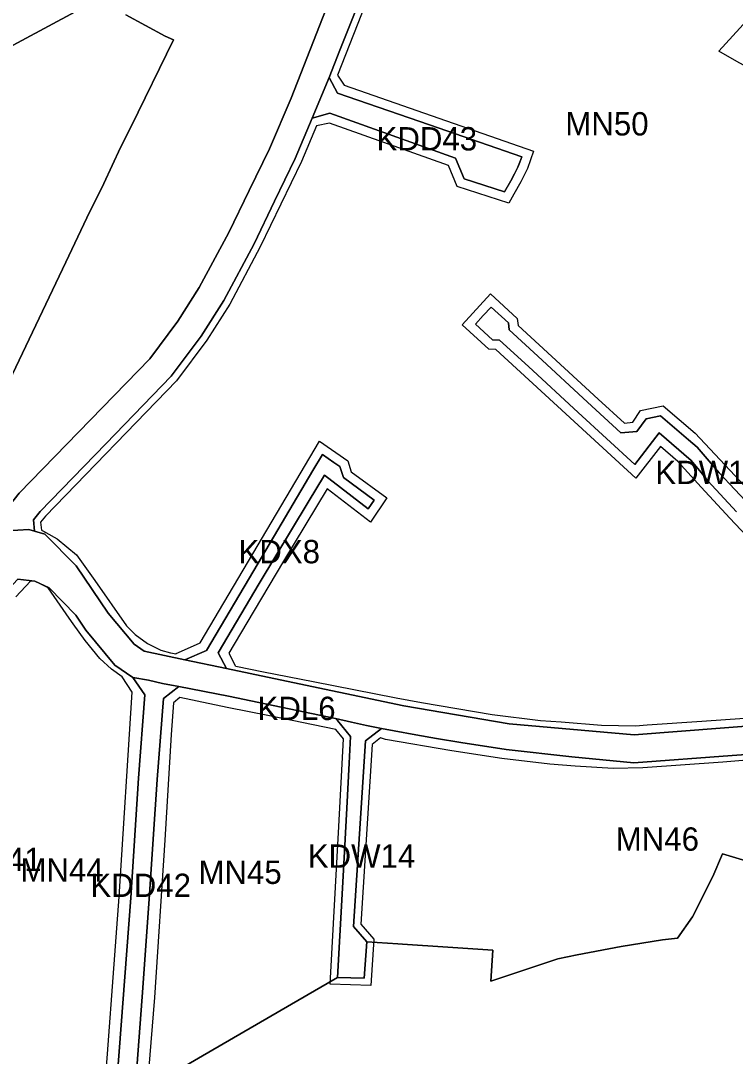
# Model space of a CAD drawing. Extents: x 7428841 to 7433518, y 5545054 to 5546840.
# Drawn here: x 7432155.6 to 7432461.8, y 5545406.8 to 5545850.4 of the extents above; entities that cross this region are included whole.
import ezdxf

# ---------------------------------------------------------------- set-up
doc = ezdxf.new("R2010")
doc.units = 0
for name, color, linetype in [('linie_rozgraniczajace', 7, 'Continuous'), ('linie_zabudowy_nieprzekraczalne', 7, 'Continuous'), ('oznaczenia_przeznaczen', 7, 'Continuous')]:
    doc.layers.add(name, color=color, linetype=linetype)

msp = doc.modelspace()

# ---------------------------------------------------------------- linework, layer by layer
at = {"layer": 'linie_rozgraniczajace'}
for points in [[(7432132.18, 5545621.69), (7432147.9, 5545639.12), (7432154.88, 5545648.03), (7432210.86, 5545705.54), (7432222.9, 5545721.64), (7432232.08, 5545736.14), (7432244.76, 5545759.7), (7432253.45, 5545777.62), (7432262.14, 5545795.55), (7432271.44, 5545817.17), (7432287.75, 5545858.73), (7432313.15, 5545921.27), (7432332.96, 5545968.95), (7432347.45, 5546006.55), (7432352.33, 5546020.89), (7432357.2, 5546035.24), (7432363.75, 5546056.3), (7432370.28, 5546073.1), (7432379.89, 5546097.52)], [(7432188.47, 5545859.56), (7432146.36, 5545836.73), (7432135.07, 5545830.88), (7432134.66, 5545831.89), (7432125.88, 5545827.16), (7432101.56, 5545814.32), (7432079.45, 5545802.66), (7432010.61, 5545766.29), (7431989.91, 5545755.55), (7431989.48, 5545756.43), (7431983.69, 5545768.63), (7431979.69, 5545777.2), (7431976.57, 5545783.86), (7431971.71, 5545794.23)], [(7432146.36, 5545836.73), (7432188.47, 5545859.56)], [(7432287.75, 5545858.73), (7432271.44, 5545817.17), (7432262.14, 5545795.55), (7432253.45, 5545777.62), (7432244.76, 5545759.7), (7432232.08, 5545736.14), (7432222.9, 5545721.64), (7432210.86, 5545705.54), (7432154.88, 5545648.03), (7432147.9, 5545639.12), (7432132.18, 5545621.69), (7432124.12, 5545622.82), (7432124.01, 5545622.95), (7432120.53, 5545626.94), (7432114.08, 5545634.7), (7432107.63, 5545642.46), (7432103.72, 5545647.14)], [(7432103.72, 5545647.14), (7432115.61, 5545651.14), (7432124.15, 5545655.2), (7432129.9, 5545658.64), (7432133.99, 5545663.57), (7432139.05, 5545671.94), (7432174.91, 5545747.04), (7432183.86, 5545765.9), (7432191.2, 5545780.73), (7432198.41, 5545796.09), (7432202.91, 5545805.04), (7432221.07, 5545842.2), (7432217.5, 5545843.79), (7432200.67, 5545852.98)], [(7432298.89, 5545854.26), (7432292.35, 5545837.77), (7432287.69, 5545826.02), (7432280.47, 5545808.59), (7432273.19, 5545791.34), (7432264.38, 5545773.09), (7432255.56, 5545754.84), (7432242.56, 5545730.56), (7432232.89, 5545715.25), (7432220.1, 5545698.07), (7432192.02, 5545669.12), (7432163.94, 5545640.18), (7432161, 5545636.55), (7432161.55, 5545631.78), (7432159.07, 5545632.52), (7432149.7, 5545631.91), (7432134.84, 5545623.57), (7432132.18, 5545621.69)], [(7432200.67, 5545852.98), (7432217.5, 5545843.79), (7432221.07, 5545842.2), (7432202.91, 5545805.04), (7432198.41, 5545796.09), (7432191.2, 5545780.73), (7432183.86, 5545765.9), (7432174.91, 5545747.04), (7432139.05, 5545671.94)], [(7432161, 5545636.55), (7432163.94, 5545640.18), (7432192.02, 5545669.12), (7432220.1, 5545698.07), (7432232.89, 5545715.25), (7432242.56, 5545730.56), (7432255.56, 5545754.84), (7432264.38, 5545773.09), (7432273.19, 5545791.34), (7432280.47, 5545808.59), (7432288.02, 5545810.74), (7432341.82, 5545791.55), (7432345.58, 5545782.71), (7432362.91, 5545777.13), (7432365.52, 5545781.77), (7432367.15, 5545784.84), (7432368.55, 5545787.63), (7432369.45, 5545789.78), (7432370.26, 5545792.08), (7432330.81, 5545805.75), (7432291.36, 5545819.41), (7432287.69, 5545826.02), (7432292.35, 5545837.77), (7432298.89, 5545854.26)], [(7432468.21, 5545642.48), (7432454.85, 5545656.77), (7432445.49, 5545667.66), (7432441.75, 5545670.86), (7432429.75, 5545681.15), (7432423.63, 5545679.82), (7432419.51, 5545674.46), (7432412.78, 5545673.88), (7432398.5, 5545687.02), (7432377.15, 5545706.66), (7432364.82, 5545718), (7432364.53, 5545721), (7432357.17, 5545727.76), (7432353.79, 5545724.08), (7432350.4, 5545720.4), (7432357.76, 5545713.64), (7432360.76, 5545713.6), (7432373.1, 5545702.24), (7432394.43, 5545682.61), (7432418.67, 5545660.3), (7432429.09, 5545673.81), (7432442.81, 5545662.06), (7432447.1, 5545656.91), (7432450.07, 5545653.35), (7432462.29, 5545640.03)], [(7432462.29, 5545640.03), (7432450.07, 5545653.35), (7432447.1, 5545656.91), (7432442.81, 5545662.06), (7432429.09, 5545673.81), (7432418.67, 5545660.3), (7432394.43, 5545682.61), (7432373.1, 5545702.24), (7432360.76, 5545713.6), (7432357.76, 5545713.64), (7432350.4, 5545720.4), (7432353.79, 5545724.08), (7432357.17, 5545727.76), (7432364.53, 5545721), (7432364.82, 5545718), (7432377.15, 5545706.66), (7432398.5, 5545687.02), (7432412.78, 5545673.88), (7432419.51, 5545674.46), (7432423.63, 5545679.82), (7432429.75, 5545681.15), (7432441.75, 5545670.86), (7432445.49, 5545667.66), (7432454.85, 5545656.77), (7432468.21, 5545642.48)], [(7432495.96, 5545550.47), (7432457.17, 5545547.49), (7432418.37, 5545544.51), (7432364.94, 5545549.16), (7432319.77, 5545556.99), (7432264.11, 5545568.64), (7432243.74, 5545572.89), (7432240.16, 5545579.64), (7432257.77, 5545609.34), (7432278.79, 5545644.13), (7432285.8, 5545655.72), (7432304.5, 5545641.34), (7432307.03, 5545645.05), (7432293.82, 5545654.7), (7432292.32, 5545659.42), (7432289.8, 5545661.17), (7432284.92, 5545664.56), (7432280.69, 5545657.77), (7432257.34, 5545617.98), (7432235.25, 5545580.69), (7432225.91, 5545576.62), (7432208.45, 5545580.28), (7432204.14, 5545583.28), (7432193.05, 5545596.6), (7432186.19, 5545606.77), (7432179.32, 5545616.95), (7432165.95, 5545630.47), (7432161.55, 5545631.78), (7432161, 5545636.55)], [(7432149.7, 5545631.91), (7432159.07, 5545632.52), (7432161.55, 5545631.78), (7432165.95, 5545630.47), (7432179.32, 5545616.95), (7432186.19, 5545606.77), (7432193.05, 5545596.6), (7432204.14, 5545583.28), (7432208.45, 5545580.28), (7432225.91, 5545576.62), (7432243.74, 5545572.89), (7432264.11, 5545568.64), (7432319.77, 5545556.99), (7432364.94, 5545549.16), (7432418.37, 5545544.51), (7432457.17, 5545547.49), (7432495.96, 5545550.47)], [(7432138.74, 5545379.48), (7432142.98, 5545436.66), (7432146.31, 5545480.82), (7432148.15, 5545499.91), (7432149.67, 5545528.57), (7432149.18, 5545545.32), (7432149.02, 5545565.9), (7432148.85, 5545586.48), (7432148.59, 5545598.65), (7432148.5, 5545604.9), (7432154.28, 5545611.17), (7432161.6, 5545610.32), (7432167.75, 5545607.49), (7432179.14, 5545595.76), (7432183.44, 5545589.39), (7432195.95, 5545574.36), (7432203.6, 5545569.04), (7432208.81, 5545561.69), (7432206.08, 5545525.88), (7432202.71, 5545474.72), (7432196.1, 5545386.25)], [(7432303.7, 5545548.56), (7432297.3, 5545549.97), (7432290.42, 5545551.44), (7432283.54, 5545552.91), (7432244.58, 5545561.06), (7432223.28, 5545565.18), (7432216.33, 5545566.52), (7432210.29, 5545567.85), (7432203.6, 5545569.04), (7432195.95, 5545574.36), (7432183.44, 5545589.39), (7432179.14, 5545595.76), (7432167.75, 5545607.49), (7432161.6, 5545610.32), (7432154.28, 5545611.17)], [(7432483.05, 5545485.51), (7432456.34, 5545493.47), (7432452.13, 5545483.85), (7432443.43, 5545466.55), (7432436.98, 5545457.38), (7432430.58, 5545456.64), (7432412.8, 5545453.79), (7432394.07, 5545450.22), (7432385.79, 5545448.51), (7432356.96, 5545439.01), (7432357.94, 5545452.26), (7432338.58, 5545453.55), (7432319.23, 5545454.85), (7432317.12, 5545454.99), (7432303.84, 5545455.89), (7432298.23, 5545462.43), (7432299.92, 5545488.83), (7432303.27, 5545541.94), (7432310.18, 5545547.28), (7432315.59, 5545546.21), (7432324.92, 5545544.5), (7432333.73, 5545542.87), (7432344.16, 5545541.23), (7432363.52, 5545538.18), (7432391.68, 5545535.1), (7432418.31, 5545532.47), (7432460.41, 5545535.59), (7432502.51, 5545538.7)], [(7432502.51, 5545538.7), (7432460.41, 5545535.59), (7432418.31, 5545532.47), (7432391.68, 5545535.1), (7432363.52, 5545538.18), (7432344.16, 5545541.23), (7432333.73, 5545542.87), (7432324.92, 5545544.5), (7432315.59, 5545546.21), (7432310.18, 5545547.28), (7432303.7, 5545548.56)], [(7432209.79, 5545393.18), (7432233.45, 5545406.94), (7432274.26, 5545430.67), (7432291.3, 5545440.58), (7432297.02, 5545440.39), (7432302.75, 5545440.2), (7432303.84, 5545455.89), (7432317.12, 5545454.99), (7432319.23, 5545454.85), (7432338.58, 5545453.55), (7432357.94, 5545452.26), (7432356.96, 5545439.01), (7432385.79, 5545448.51), (7432394.07, 5545450.22), (7432412.8, 5545453.79), (7432430.58, 5545456.64), (7432436.98, 5545457.38), (7432443.43, 5545466.55), (7432452.13, 5545483.85), (7432456.34, 5545493.47), (7432483.05, 5545485.51)]]:
    msp.add_lwpolyline(points, dxfattribs=at)
for points in [[(7432280.47, 5545808.59), (7432287.69, 5545826.02), (7432291.36, 5545819.41), (7432330.81, 5545805.75), (7432370.26, 5545792.08), (7432369.45, 5545789.78), (7432368.55, 5545787.63), (7432367.15, 5545784.84), (7432365.52, 5545781.77), (7432362.91, 5545777.13), (7432345.58, 5545782.71), (7432341.82, 5545791.55), (7432288.02, 5545810.74)], [(7432225.91, 5545576.62), (7432235.25, 5545580.69), (7432257.34, 5545617.98), (7432280.69, 5545657.77), (7432284.92, 5545664.56), (7432289.8, 5545661.17), (7432292.32, 5545659.42), (7432293.82, 5545654.7), (7432307.03, 5545645.05), (7432304.5, 5545641.34), (7432285.8, 5545655.72), (7432278.79, 5545644.13), (7432257.77, 5545609.34), (7432240.16, 5545579.64), (7432243.74, 5545572.89)], [(7432196.1, 5545386.25), (7432202.71, 5545474.72), (7432206.08, 5545525.88), (7432208.81, 5545561.69), (7432203.6, 5545569.04), (7432210.29, 5545567.85), (7432216.33, 5545566.52), (7432223.28, 5545565.18), (7432216.71, 5545560.01), (7432214.06, 5545525.32), (7432212.38, 5545499.74), (7432210.69, 5545474.16), (7432207.56, 5545432.32), (7432204.44, 5545390.47), (7432203.54, 5545390.02), (7432197.14, 5545386.77)], [(7432204.44, 5545390.47), (7432207.56, 5545432.32), (7432210.69, 5545474.16), (7432212.38, 5545499.74), (7432214.06, 5545525.32), (7432216.71, 5545560.01), (7432223.28, 5545565.18), (7432244.58, 5545561.06), (7432283.54, 5545552.91), (7432290.42, 5545551.44), (7432291.32, 5545550.69), (7432296.95, 5545543.74), (7432296.3, 5545532.35), (7432295.25, 5545513.02), (7432294.01, 5545489.23), (7432293.34, 5545476.24), (7432291.3, 5545440.58), (7432274.26, 5545430.67), (7432233.45, 5545406.94), (7432209.79, 5545393.18)], [(7432291.3, 5545440.58), (7432293.34, 5545476.24), (7432294.01, 5545489.23), (7432295.25, 5545513.02), (7432296.3, 5545532.35), (7432296.95, 5545543.74), (7432291.32, 5545550.69), (7432290.42, 5545551.44), (7432297.3, 5545549.97), (7432303.7, 5545548.56), (7432310.18, 5545547.28), (7432303.27, 5545541.94), (7432299.92, 5545488.83), (7432298.23, 5545462.43), (7432303.84, 5545455.89), (7432302.75, 5545440.2), (7432297.02, 5545440.39)]]:
    msp.add_lwpolyline(points, close=True, dxfattribs=at)
at = {"layer": 'linie_zabudowy_nieprzekraczalne'}
for points in [[(7432553.71, 5545656.87), (7432535.29, 5545673.24), (7432519.45, 5545687.14), (7432507.2, 5545698.97), (7432503.13, 5545703.79), (7432500.72, 5545708.71), (7432499.42, 5545713.29), (7432491.95, 5545778.42), (7432488.57, 5545817.36), (7432487.85, 5545818.9), (7432476.64, 5545826.01), (7432470.39, 5545828.94), (7432465.86, 5545831.11), (7432463.4, 5545832.33), (7432454.78, 5545837.43), (7432478.74, 5545863.82), (7432512.66, 5545902.33), (7432533.86, 5545927.37), (7432576.75, 5545979.38), (7432604.6, 5546013.61), (7432608.93, 5546021.42)], [(7432363.46, 5546007.84), (7432361.46, 5546001.7), (7432346.89, 5545963.38), (7432336.96, 5545939.48), (7432314.35, 5545884.36), (7432301.67, 5545853.15), (7432291.29, 5545827.01)], [(7432291.29, 5545827.01), (7432294.14, 5545822.86), (7432334.74, 5545808.62), (7432375.37, 5545794.54), (7432372.69, 5545787.15), (7432371.45, 5545784.48), (7432369.87, 5545781.43), (7432366.91, 5545776.09), (7432364.79, 5545772.32), (7432342.61, 5545779.46), (7432338.83, 5545788.37), (7432287.89, 5545806.54), (7432282.29, 5545805.32)], [(7432282.29, 5545805.32), (7432275.93, 5545790.1), (7432258.24, 5545753.48), (7432245.15, 5545729.05), (7432235.36, 5545713.55), (7432222.39, 5545696.12), (7432166.19, 5545638.18), (7432164.12, 5545635.64), (7432164.53, 5545632.12)], [(7432473.62, 5545622.28), (7432459.36, 5545637.3), (7432447.11, 5545650.66), (7432437.15, 5545661.64), (7432429.69, 5545668.03), (7432419.18, 5545654.4), (7432359.18, 5545709.62), (7432356.18, 5545709.66), (7432344.75, 5545720.16), (7432356.93, 5545733.41), (7432368.36, 5545722.9), (7432368.66, 5545719.91), (7432403, 5545688.31), (7432414.3, 5545678.03), (7432417.92, 5545678.42), (7432421.18, 5545683.38), (7432430.84, 5545685.48), (7432444.52, 5545673.75), (7432484.92, 5545630.57)], [(7432221.9, 5545579.24), (7432232.47, 5545583.84), (7432283.67, 5545670.3), (7432295.73, 5545661.93), (7432297.24, 5545657.15), (7432312.52, 5545645.99), (7432305.41, 5545635.59), (7432286.91, 5545649.82), (7432268.2, 5545618.88), (7432252.4, 5545592.45), (7432244.73, 5545579.52), (7432247.63, 5545573.88)], [(7432164.53, 5545632.12), (7432165.57, 5545631.65), (7432166.41, 5545631.18), (7432171.23, 5545628.49), (7432175.37, 5545625.01), (7432179.51, 5545621.54), (7432187.28, 5545610.62), (7432200.95, 5545591.12), (7432204.64, 5545587.45), (7432209.95, 5545583.67), (7432215.58, 5545580.82), (7432219.83, 5545579.6), (7432222.21, 5545579.13)], [(7432199.08, 5545569.34), (7432194.45, 5545572.64), (7432189.54, 5545577.26), (7432183.25, 5545584.92), (7432178.01, 5545592.04), (7432176.32, 5545594.45), (7432167.31, 5545607.42), (7432161.6, 5545610.32), (7432159.81, 5545610.31), (7432153.54, 5545603.66)], [(7432247.77, 5545573.92), (7432259.56, 5545571.46), (7432280.88, 5545567.35), (7432316.46, 5545560.32), (7432327.27, 5545558.29), (7432357.63, 5545553.16), (7432378.33, 5545550.62), (7432387.21, 5545550.01), (7432404.47, 5545548.7), (7432419.02, 5545548.35), (7432424.04, 5545548.71), (7432447.45, 5545550.3), (7432473.79, 5545552.27), (7432489.45, 5545553.01), (7432497.43, 5545553.34), (7432506.55, 5545553.25), (7432514.8, 5545552.66)], [(7432223.73, 5545560.44), (7432221, 5545558.27), (7432220.04, 5545544.59), (7432217.35, 5545499.4), (7432212.89, 5545431.96), (7432209.35, 5545388.08), (7432190.54, 5545377.1), (7432197.72, 5545475.06), (7432203.3, 5545562.75), (7432199.08, 5545569.34)], [(7432290.57, 5545546.85), (7432262.14, 5545552.65), (7432244.04, 5545556.17), (7432231.24, 5545558.85), (7432223.73, 5545560.44)], [(7432309.79, 5545543.2), (7432306.18, 5545540.4), (7432301.31, 5545463.46), (7432306.92, 5545456.9), (7432305.54, 5545437.1), (7432288.13, 5545437.69), (7432291.86, 5545505.24), (7432293.89, 5545542.76), (7432290.57, 5545546.85)], [(7432607.74, 5545514.22), (7432597.67, 5545516.99), (7432566.17, 5545524.4), (7432540.88, 5545529.57), (7432528.76, 5545532.18), (7432515.92, 5545534.17), (7432502.41, 5545535.32), (7432497.8, 5545535.52), (7432482.16, 5545534.88), (7432456.41, 5545532.76), (7432422.18, 5545530.37), (7432409.49, 5545530.11), (7432393.21, 5545531.14), (7432382.31, 5545531.96), (7432361.79, 5545534.32), (7432340.31, 5545537.64), (7432311.94, 5545542.49), (7432309.79, 5545543.2)]]:
    msp.add_lwpolyline(points, dxfattribs=at)

# ---------------------------------------------------------------- texts
at = {"layer": 'oznaczenia_przeznaczen'}
for s, p in [('MN50', (7432388.94, 5545801.24)), ('KDD43', (7432308.04, 5545794.83)), ('KDW16', (7432427.49, 5545651.91)), ('KDX8', (7432248.89, 5545617.98)), ('KDL6', (7432257.05, 5545550.83)), ('MN46', (7432410.53, 5545494.86)), ('KDD41', (7432121.45, 5545486.1)), ('KDW14', (7432278.58, 5545487.56)), ('MN44', (7432155.46, 5545481.55)), ('MN45', (7432231.74, 5545480.63)), ('KDD42', (7432185.44, 5545475.02))]:
    msp.add_text(s, height=10, dxfattribs=at).set_placement(p)

doc.saveas('drawing.dxf')
